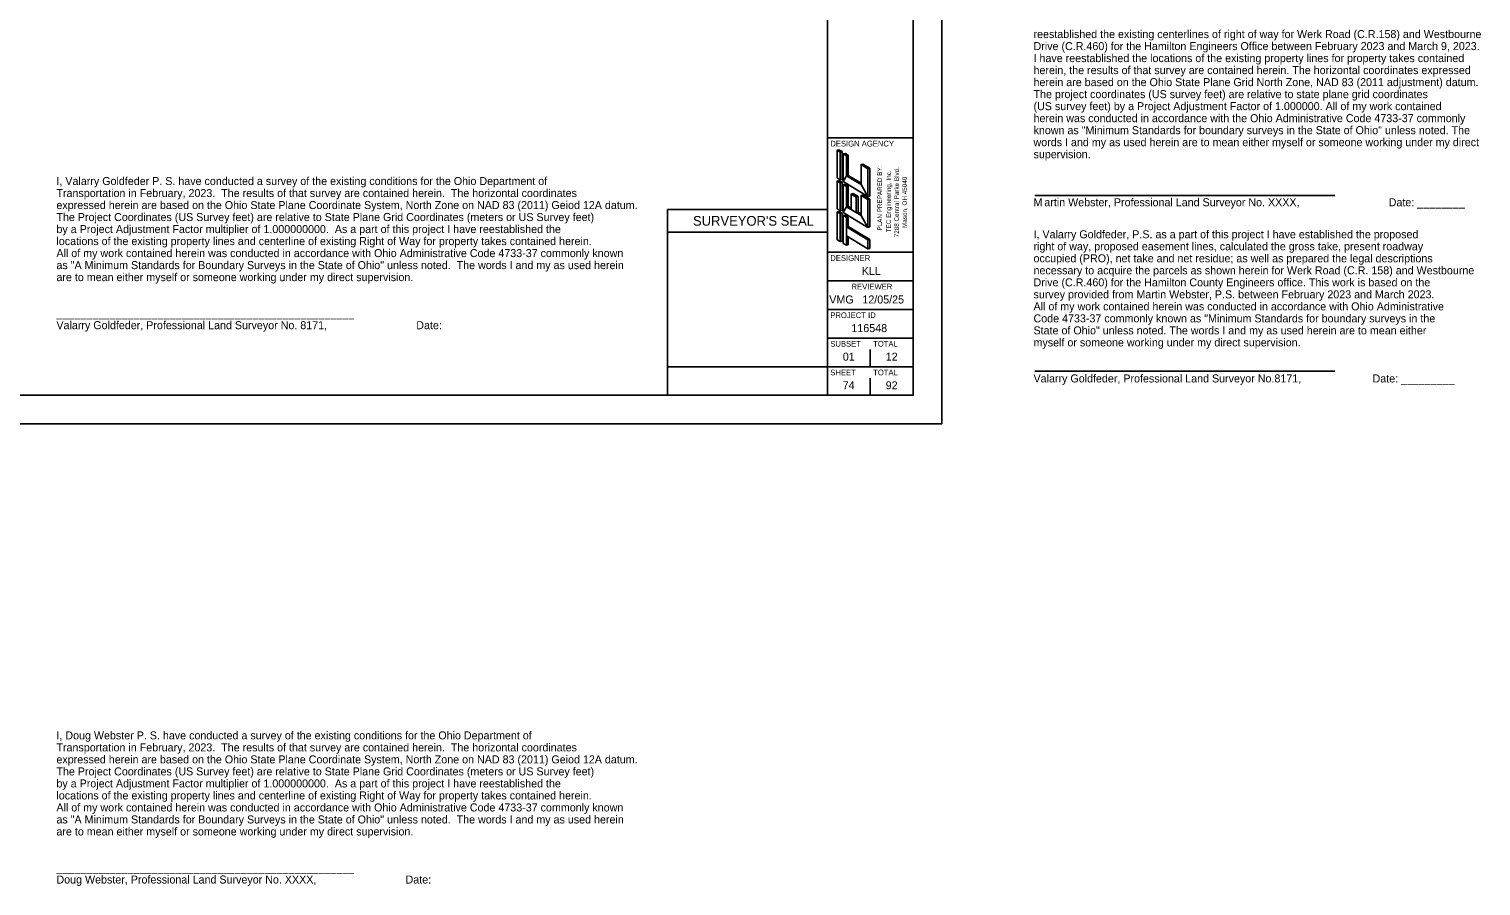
# Model space of a CAD drawing. Extents: x 0 to 43.4, y -8.1 to 22.
# Drawn here: x 18.03 to 43.43, y -8.08 to 6.9 of the extents above; entities that cross this region are included whole.
import ezdxf

# ---------------------------------------------------------------- set-up
doc = ezdxf.new("R2010")
doc.units = 0
for name, color, linetype in [('Default', 7, 'Continuous'), ('SH_Border', 7, 'Continuous'), ('SH_Cut_Line', 7, 'Continuous'), ('SH_Data', 7, 'Continuous'), ('SH_Text', 7, 'Continuous')]:
    doc.layers.add(name, color=color, linetype=linetype)

msp = doc.modelspace()

# ---------------------------------------------------------------- linework, layer by layer
at = {"layer": 'SH_Border'}
for p, q in [((32, 0.5), (32, 21.5)), ((32, 5), (33.5, 5)), ((32, 3), (33.5, 3)), ((32, 2.5), (33.5, 2.5)), ((32, 2), (33.5, 2)), ((32, 1.5), (33.5, 1.5)), ((32, 1), (33.5, 1))]:
    msp.add_line(p, q, dxfattribs=at)
msp.add_lwpolyline([(1.5, 21.5), (33.5, 21.5), (33.5, 0.5), (1.5, 0.5)], close=True, dxfattribs=at)
at = {"layer": 'SH_Cut_Line'}
msp.add_lwpolyline([(0, 0), (34, 0), (34, 22), (0, 22)], close=True, dxfattribs=at)
at = {"layer": 'SH_Data'}
for p, q in [((32.75, 4), (32.75, 4)), ((32, 3.75), (29.2, 3.75)), ((29.2, 3.75), (29.2, 0.5)), ((32, 3.35), (29.2, 3.35)), ((32.75, 1), (32.75, 1.3)), ((32.75, 0.5), (32.75, 0.8)), ((32.375, 0.675), (32.375, 0.675))]:
    msp.add_line(p, q, dxfattribs=at)
msp.add_lwpolyline([(32, 0.5), (32, 1), (29.2, 1), (29.2, 0.5)], close=True, dxfattribs=at)
at = {"layer": 'SH_Text'}
for p, q in [((32.169, 4.785), (32.201, 4.794)), ((32.169, 4.299), (32.169, 4.785)), ((32.223, 4.753), (32.169, 4.785)), ((32.255, 4.761), (32.201, 4.794)), ((32.223, 4.753), (32.255, 4.761)), ((32.223, 4.267), (32.223, 4.753)), ((32.255, 4.275), (32.255, 4.761)), ((32.277, 4.721), (32.309, 4.729)), ((32.331, 4.688), (32.277, 4.721)), ((32.277, 4.235), (32.277, 4.721)), ((32.309, 4.729), (32.363, 4.696)), ((32.331, 4.688), (32.363, 4.696)), ((32.331, 4.337), (32.331, 4.688)), ((32.363, 4.696), (32.363, 4.345)), ((32.331, 4.337), (32.363, 4.345)), ((32.587, 4.183), (32.331, 4.337)), ((32.363, 4.345), (32.587, 4.211)), ((32.587, 4.534), (32.62, 4.542)), ((32.587, 4.183), (32.587, 4.534)), ((32.709, 4.461), (32.587, 4.534)), ((32.62, 4.542), (32.741, 4.47)), ((32.709, 4.461), (32.741, 4.47)), ((32.709, 3.975), (32.709, 4.461)), ((32.741, 4.47), (32.741, 3.984)), ((32.223, 4.267), (32.169, 4.299)), ((32.169, 4.245), (32.201, 4.254)), ((32.169, 3.759), (32.169, 4.245)), ((32.223, 4.213), (32.169, 4.245)), ((32.255, 4.222), (32.201, 4.254)), ((32.223, 4.267), (32.255, 4.275)), ((32.223, 4.213), (32.255, 4.222)), ((32.223, 3.727), (32.223, 4.213)), ((32.255, 3.736), (32.255, 4.222)), ((32.709, 3.975), (32.277, 4.235)), ((32.277, 4.181), (32.309, 4.189)), ((32.277, 3.695), (32.277, 4.181)), ((32.331, 4.148), (32.277, 4.181)), ((32.309, 4.189), (32.363, 4.156)), ((32.331, 4.148), (32.363, 4.156)), ((32.331, 3.797), (32.331, 4.148)), ((32.363, 4.156), (32.363, 3.805)), ((32.415, 4.019), (32.448, 4.027)), ((32.415, 4.019), (32.415, 3.747)), ((32.415, 4.019), (32.503, 3.966)), ((32.448, 4.027), (32.535, 3.974)), ((32.503, 3.966), (32.535, 3.974)), ((32.503, 3.966), (32.503, 3.694)), ((32.535, 3.974), (32.535, 3.702)), ((32.587, 3.994), (32.62, 4.002)), ((32.587, 3.643), (32.587, 3.994)), ((32.709, 3.921), (32.587, 3.994)), ((32.62, 4.002), (32.741, 3.93)), ((32.709, 3.975), (32.741, 3.984)), ((32.709, 3.921), (32.741, 3.93)), ((32.709, 3.435), (32.709, 3.921)), ((32.741, 3.93), (32.741, 3.444)), ((35.629, 3.994), (40.878, 3.994)), ((32.223, 3.727), (32.169, 3.759)), ((32.169, 3.705), (32.201, 3.715)), ((32.169, 3.219), (32.169, 3.705)), ((32.223, 3.673), (32.169, 3.705)), ((32.255, 3.681), (32.201, 3.715)), ((32.222, 3.673), (32.255, 3.681)), ((32.223, 3.727), (32.255, 3.736)), ((32.223, 3.187), (32.223, 3.673)), ((32.255, 3.195), (32.255, 3.681)), ((32.709, 3.435), (32.277, 3.695)), ((32.277, 3.641), (32.309, 3.651)), ((32.331, 3.608), (32.277, 3.641)), ((32.277, 3.155), (32.277, 3.641)), ((32.309, 3.651), (32.363, 3.616)), ((32.331, 3.797), (32.363, 3.805)), ((32.415, 3.747), (32.331, 3.797)), ((32.331, 3.608), (32.363, 3.616)), ((32.331, 3.444), (32.331, 3.608)), ((32.363, 3.805), (32.415, 3.774)), ((32.363, 3.616), (32.363, 3.452)), ((32.503, 3.694), (32.535, 3.702)), ((32.587, 3.643), (32.503, 3.694)), ((32.535, 3.702), (32.587, 3.671)), ((32.331, 3.444), (32.363, 3.452)), ((32.331, 3.444), (32.709, 3.217)), ((32.363, 3.452), (32.741, 3.225)), ((32.709, 3.435), (32.741, 3.444)), ((32.223, 3.187), (32.169, 3.219)), ((32.223, 3.187), (32.255, 3.195)), ((32.331, 3.122), (32.277, 3.155)), ((32.331, 3.287), (32.709, 3.06)), ((32.331, 3.122), (32.331, 3.287)), ((32.331, 3.122), (32.363, 3.13)), ((32.363, 3.13), (32.363, 3.267)), ((32.709, 3.217), (32.741, 3.225)), ((32.709, 3.06), (32.709, 3.217)), ((32.709, 3.06), (32.741, 3.068)), ((32.741, 3.225), (32.741, 3.068)), ((35.629, 0.921), (40.878, 0.921))]:
    msp.add_line(p, q, dxfattribs=at)
for points in [[(32.169, 4.299), (32.223, 4.267), (32.223, 4.753), (32.169, 4.785)], [(32.277, 4.235), (32.331, 4.337), (32.331, 4.688), (32.277, 4.721)], [(32.277, 4.235), (32.331, 4.337), (32.587, 4.183), (32.709, 3.975)], [(32.709, 3.975), (32.587, 4.183), (32.587, 4.534), (32.709, 4.461)], [(32.169, 3.759), (32.223, 3.727), (32.223, 4.213), (32.169, 4.245)], [(32.277, 3.695), (32.331, 3.797), (32.331, 4.148), (32.277, 4.181)], [(32.415, 3.747), (32.415, 4.019), (32.503, 3.966), (32.503, 3.694)], [(32.709, 3.435), (32.587, 3.643), (32.587, 3.994), (32.709, 3.921)], [(29.2, 3.75), (32, 3.75), (32, 0.5), (29.2, 0.5)], [(32.169, 3.219), (32.223, 3.187), (32.223, 3.673), (32.169, 3.705)], [(32.277, 3.695), (32.331, 3.797), (32.587, 3.643), (32.709, 3.435)], [(32.277, 3.155), (32.331, 3.122), (32.331, 3.608), (32.277, 3.641)], [(32.331, 3.287), (32.331, 3.444), (32.709, 3.217), (32.709, 3.06)]]:
    msp.add_lwpolyline(points, close=True, dxfattribs=at)

# ---------------------------------------------------------------- texts
at = {"layer": 'Default'}
for s, p in [('PLAN PREPARED BY:', (32.954, 3.38)), ('TEC Engineering, Inc.', (33.11, 3.351)), ('7288 Central Parke Blvd.', (33.25, 3.262)), ('Mason, OH 45040', (33.39, 3.425))]:
    msp.add_text(s, height=0.08, rotation=90, dxfattribs=at).set_placement(p)
at = {"layer": 'SH_Data'}
for s, height, p in [('DESIGN AGENCY', 0.1, (32.05, 4.85)), ("SURVEYOR'S SEAL", 0.17, (29.648, 3.465)), ('DESIGNER', 0.1, (32.05, 2.85)), ('KLL', 0.14, (32.601, 2.605)), ('REVIEWER', 0.1, (32.422, 2.35)), ('VMG', 0.14, (32.032, 2.105)), ('12/05/25', 0.14, (32.611, 2.105)), ('PROJECT ID', 0.1, (32.05, 1.85)), ('116548', 0.14, (32.419, 1.605)), ('SUBSET', 0.1, (32.05, 1.35)), ('TOTAL', 0.1, (32.8, 1.35)), ('01', 0.14, (32.269, 1.105)), ('12', 0.14, (33.019, 1.105)), ('SHEET', 0.1, (32.05, 0.85)), ('TOTAL', 0.1, (32.8, 0.85)), ('74', 0.14, (32.266, 0.605)), ('92', 0.14, (33.019, 0.605))]:
    msp.add_text(s, height=height, dxfattribs=at).set_placement(p)
at = {"layer": 'SH_Text'}
for s, p in [('reestablished the existing centerlines of right of way for Werk Road (C.R.158) and Westbourne', (35.605, 6.745)), ('Drive (C.R.460) for the Hamilton Engineers Office between February 2023 and March 9, 2023.', (35.605, 6.535)), ('I have reestablished the locations of the existing property lines for property takes contained', (35.605, 6.325)), ('herein, the results of that survey are contained herein. The horizontal coordinates expressed', (35.605, 6.115)), ('The project coordinates (US survey feet) are relative to state plane grid coordinates', (35.605, 5.695)), ('herein are based on the Ohio State Plane Grid North Zone, NAD 83 (2011 adjustment) datum.', (35.605, 5.905)), ('(US survey feet) by a Project Adjustment Factor of 1.000000. All of my work contained', (35.605, 5.485)), ('herein was conducted in accordance with the Ohio Administrative Code 4733-37 commonly', (35.605, 5.275)), ('known as "Minimum Standards for boundary surveys in the State of Ohio" unless noted. The', (35.605, 5.065)), ('words I and my as used herein are to mean either myself or someone working under my direct', (35.605, 4.855)), ('supervision.', (35.605, 4.645)), ('I, Valarry Goldfeder P. S. have conducted a survey of the existing conditions for the Ohio Department of', (18.512, 4.176)), ('Transportation in February, 2023.  The results of that survey are contained herein.  The horizontal coordinates', (18.512, 3.966)), ('expressed herein are based on the Ohio State Plane Coordinate System, North Zone on NAD 83 (2011) Geiod 12A datum.', (18.512, 3.756)), ('M', (35.605, 3.805)), ('artin Webster, Professional Land Surveyor No. XXXX,                              Date: ________', (35.794, 3.805)), ('The Project Coordinates (US Survey feet) are relative to State Plane Grid Coordinates (meters or US Survey feet)', (18.512, 3.546)), ('by a Project Adjustment Factor multiplier of 1.000000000.  As a part of this project I have reestablished the', (18.512, 3.336)), ('I, Valarry Goldfeder, P.S. as a part of this project I have established the proposed', (35.605, 3.245)), ('All of my work contained herein was conducted in accordance with Ohio Administrative Code 4733-37 commonly known', (18.512, 2.916)), ('locations of the existing property lines and centerline of existing Right of Way for property takes contained herein.  ', (18.512, 3.126)), ('right of way, proposed easement lines, calculated the gross take, present roadway', (35.605, 3.035)), ('as "A Minimum Standards for Boundary Surveys in the State of Ohio" unless noted.  The words I and my as used herein', (18.512, 2.706)), ('occupied (PRO), net take and net residue; as well as prepared the legal descriptions', (35.605, 2.825)), ('are to mean either myself or someone working under my direct supervision.', (18.512, 2.496)), ('necessary to acquire the parcels as shown herein for Werk Road (C.R. 158) and Westbourne', (35.605, 2.615)), ('Drive (C.R.460) for the Hamilton County Engineers office. This work is based on the ', (35.605, 2.405)), ('survey provided from Martin Webster, P.S. between February 2023 and March 2023. ', (35.605, 2.195)), ('All of my work contained herein was conducted in accordance with Ohio Administrative ', (35.605, 1.985)), ('__________________________________________________', (18.512, 1.866)), ('Valarry Goldfeder, Professional Land Surveyor No. 8171,                              Date:                ', (18.512, 1.656)), ('Code 4733-37 commonly known as "Minimum Standards for boundary surveys in the ', (35.605, 1.775)), ('State of Ohio" unless noted. The words I and my as used herein are to mean either ', (35.605, 1.565)), ('myself or someone working under my direct supervision.', (35.605, 1.355)), ('Valarry Goldfeder, Professional Land Surveyor No.8171,                        Date: _________', (35.605, 0.725)), ('Transportation in February, 2023.  The results of that survey are contained herein.  The horizontal coordinates', (18.512, -5.725)), ('I, Doug Webster P. S. have conducted a survey of the existing conditions for the Ohio Department of', (18.512, -5.515)), ('expressed herein are based on the Ohio State Plane Coordinate System, North Zone on NAD 83 (2011) Geiod 12A datum.', (18.512, -5.935)), ('The Project Coordinates (US Survey feet) are relative to State Plane Grid Coordinates (meters or US Survey feet)', (18.512, -6.145)), ('by a Project Adjustment Factor multiplier of 1.000000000.  As a part of this project I have reestablished the', (18.512, -6.355)), ('locations of the existing property lines and centerline of existing Right of Way for property takes contained herein.  ', (18.512, -6.565)), ('All of my work contained herein was conducted in accordance with Ohio Administrative Code 4733-37 commonly known', (18.512, -6.775)), ('as "A Minimum Standards for Boundary Surveys in the State of Ohio" unless noted.  The words I and my as used herein', (18.512, -6.985)), ('are to mean either myself or someone working under my direct supervision.', (18.512, -7.195)), ('__________________________________________________', (18.512, -7.825)), ('Doug Webster, Professional Land Surveyor No. XXXX,                              Date:                ', (18.512, -8.035))]:
    msp.add_text(s, height=0.14, dxfattribs=at).set_placement(p)

doc.saveas('drawing.dxf')
